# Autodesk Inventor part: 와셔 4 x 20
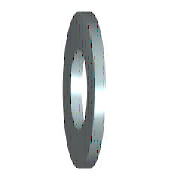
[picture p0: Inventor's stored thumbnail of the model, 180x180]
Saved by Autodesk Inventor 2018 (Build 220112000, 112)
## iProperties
IsCustomPart: 1
Created: 2012-02
Part Number: 와셔 4 x 20
Material: 강철, 연강
Description: 미터법 평면 와셔
Document SubType Name: Modeling
Standard: ANSI B18.22M
Designer: mduedu
Standard Revision: 1999
Standards Organization: ANSI
Language: ko-KR
Size Designation: 4 W
Categories: <MemberInstance><Categories><Category DisplayName="조임쇠" InternalName="e4da775c-781d-43d5-af7c-5136215cf5a6" Mnemonic="FSTN"><Category DisplayName="와셔" InternalN
Density: 1 g/cm^3
Appearance: 파란색 - 벽 페인트 - 광택
Author: mduedu
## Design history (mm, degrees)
sketch "스케치"
  geometry: C1 r 10 at (0, 0); C2 r 2.35 at (0, 0); 1 further point
  constraints: 2 centre point, 2 coincident
  dimensions: "d0" = 4.7 diameter of C2 (= SD1); "d1" = 20 diameter of C1 (= SD2)
extrude "본체" new body sketch "스케치" distance "d2" = 2.3 (= SD); taper "d3" = 0 deg
workaxis "Work Axis1"
workplane "Work Plane1"
body "Solid1"
other parameters: "SD1" = 4.7 [user parameter; used in 1 equation term], "SD2" = 20 [user parameter; used in 1 equation term], "SD" = 2.3 [user parameter; used in 1 equation term], "d4" = 0, "d5" = 0, "d6" = 0, "d7" = 0, "NND" = 4 [user parameter]
